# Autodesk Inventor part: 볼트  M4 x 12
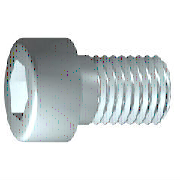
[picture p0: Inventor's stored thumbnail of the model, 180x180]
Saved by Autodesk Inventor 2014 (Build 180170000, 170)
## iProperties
IsCustomPart: 0
Created: 2015-12
Part Number: 볼트  M4 x 12
Material: 스테인리스강
Description: 6각머리 태핑 나사
Document SubType Name: Modeling
Standard: KS B 1003
Designer: mdu
Standards Organization: KS
Language: ko-KR
Size Designation: M 4 x 12
Categories: <MemberInstance><Categories><Category DisplayName="조임쇠" InternalName="e4da775c-781d-43d5-af7c-5136215cf5a6" Mnemonic="FSTN"><Category DisplayName="볼트" InternalN
Density: 8.08 g/cm^3
Mass: 2.29719 g
Surface Area: 3.30853 cm^2
Volume: 0.284306 cm^3
Appearance: 반광택
Author: mdu
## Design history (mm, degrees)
sketch "스케치1"
  geometry: L1 (-1, 0)-(12, 0); L2 (12, 0)-(12, 2); L3 (12, 2)-(1.75, 2); L4 (1.75, 2)-(1.32, 2); L5 (1.32, 2)-(0, 2); L6 (0, 2)-(0, 3.5); L7 (0, 3.5)-(-4, 3.5); L8 (-4, 3.5)-(-4, 1.732); L9 (-4, 1.732)-(-2, 1.732); L10 (-2, 1.732)-(-1, 0); L11 (-7.2, 0)-(15.2, 0) reference; L12 (0, -0.7)-(0, 4.2) reference; L13 (1.75, 2)-(0, 2)
  constraints: 22 end point, 6 parallel, 2 collinear, 2 perpendicular, 1 horizontal, 1 point on line
  dimensions: "d1" = 10.25 distance from line of L3.end L2 (= GEL); "d2" = 0.42952 distance of L4.end L3.end (computed from GAL); "d3" = 4 distance between parallel lines of L8 L6 (= KOH); "d4" = 2 distance of L8.end L9.end (= INTI); "d5" = 60 deg angle of L10 L1; "d6" = 4 diameter of L3 L1 (= GD); "d7" = 4 diameter of L5 L1 (= BDM); "d8" = 3.4641 diameter of L9 L1 (= 1.1547 x SW); "d9" = 7 diameter of L7 L1 (= KOD); "d26" = 12 distance between parallel lines of L12 L2 (= NLG)
revolve "본체" sketch "스케치1" stored, may be unused: angle "d10" = 90 deg
sketch "스케치2"
  geometry: L1 (0, -4.9)-(0, 4.9) reference; L2 (-4.9, 0)-(4.9, 0) reference; L3 (1.732, 0)-(0.866, -1.5); L4 (0.866, -1.5)-(-0.866, -1.5); L5 (-0.866, -1.5)-(-1.732, 0); L6 (-1.732, 0)-(-0.866, 1.5); L7 (-0.866, 1.5)-(0.866, 1.5); L8 (0.866, 1.5)-(1.732, 0); 2 further points
  constraints: 12 end point, 1 coincident, 1 horizontal alignment, 1 point on line, 12 other
extrude "슬롯" join sketch "스케치2" stored distance "d11" = 10; taper "d12" = 0 deg
workplane "Work Plane1"
fillet "Fillet2" dims "d30" = 0.1 (= R)
body "Solid1"
fillet "모깎기1" dims "d17" = 0.4 (= RR)
feature "스레드" dims "d13" = 10.25 (= GEL), "d14" = 0
chamfer "모따기1" distance "d15" = 0.42941 (= -0.5 x SPD + 0.5 x GD); stored, may be unused: second distance "d16" = 0.42941 (= GUL), angle "d27" = 45 deg
other parameters: "GD" = 4 (= NND) [user parameter; used in 2 equation terms], "NLG" = 12 [user parameter; used in 1 equation term], "GEL" = 10.25 [user parameter; used in 2 equation terms], "KOD" = 7 [user parameter; used in 1 equation term], "KOH" = 4 [user parameter; used in 1 equation term], "INTI" = 2 [user parameter; used in 1 equation term], "GAL" = 0.42941 (= 0.61345 x PTC) [user parameter; used in 1 equation term], "GUL" = 0.42941 (= 0.61345 x PTC) [user parameter; used in 1 equation term], "BDM" = 4 (= NND) [user parameter; used in 1 equation term], "SW" = 3 [user parameter; used in 2 equation terms], "RR" = 0.4 [user parameter; used in 1 equation term], "SPD" = 3.14117 (= NND - 1.2269 x PTC) [user parameter; used in 1 equation term], "d19" = 0, "d28" = 0, "d29" = 0, "R" = 0.1 [user parameter; used in 1 equation term], "PHH" = 0.2 [user parameter], "GD1" = 3.14117 (= THREADDIA - 1.2269 x PTC) [user parameter], "THREADDIA" = 4 [user parameter; used in 1 equation term], "FAWI" = 45 deg [user parameter], "TPU" = 14.28571 (computed from PTC) [user parameter], "PTC" = 0.7 [user parameter; used in 5 equation terms], "NND" = 4 [user parameter; used in 3 equation terms], "TOA" = 30 deg [user parameter], "E0" = 3.465 (= 1.155 x SW) [user parameter]
